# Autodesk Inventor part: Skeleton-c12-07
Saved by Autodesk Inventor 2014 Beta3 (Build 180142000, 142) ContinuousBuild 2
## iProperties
Created: 2011-01
Part Number: Skeleton-c12-07
Material: Generic
Document SubType Name: Modeling
Designer: Thom Tremblay
Density: 1 g/cm^3
Appearance: Generic
_SkeletonDoc: Frame Skeleton File
_Version: 15.0.0
Author: Thom Tremblay
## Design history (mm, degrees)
sketch "Reference Skeleton"
  geometry: L1 through (404.523, 1164.395) direction (1, 0); L2 through (325.691, 1070.446) direction (1, 0); 34 other entities
  constraints: 10 horizontal
